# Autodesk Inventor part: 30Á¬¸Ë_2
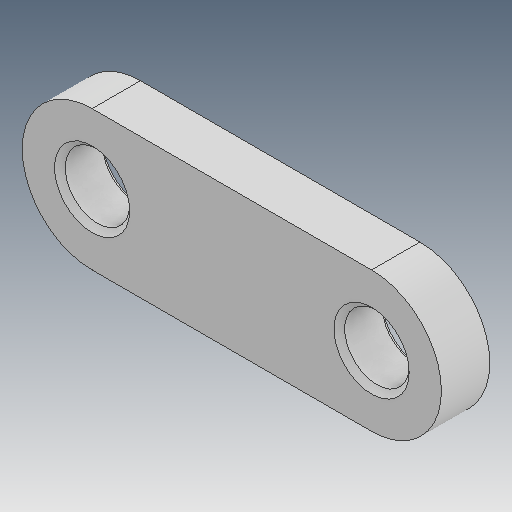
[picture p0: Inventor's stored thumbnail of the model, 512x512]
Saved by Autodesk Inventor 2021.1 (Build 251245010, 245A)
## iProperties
Created: 2019-04
Part Number: 30Á¬¸Ë_2
Material: Ogólny
Document SubType Name: Modeling
Designer: user
Density: 1 g/cm^3
Appearance: Domyślna
Author: user
Revision Number: ÈÎºÎ
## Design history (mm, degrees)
feature "ÊäÈë1"
node "Bryła1"
